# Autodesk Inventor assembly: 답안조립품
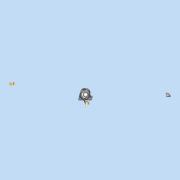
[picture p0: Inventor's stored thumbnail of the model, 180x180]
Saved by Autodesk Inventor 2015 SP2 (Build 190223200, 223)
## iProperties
Created: 2015-06
Part Number: 답안조립품
Document SubType Name: Assembly
Designer: AMC
Author: AMC
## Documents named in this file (13)
- C:\Users\AMC\Desktop\450606V1028\답안조립품.iam
- C:\Users\AMC\Desktop\450606V1028\본체.ipt
- C:\Users\AMC\Desktop\450606V1028\베어링 6204.ipt
- C:\Users\AMC\Desktop\450606V1028\크랭크 서브축.ipt
- C:\Users\AMC\Desktop\450606V1028\커넥팅 로드.ipt
- C:\Users\AMC\Desktop\450606V1028\베어링 NA 4902.ipt
- C:\Users\AMC\Desktop\450606V1028\메인 크랭크 축-구동부.ipt
- C:\Users\AMC\Desktop\450606V1028\메인커버.ipt
- C:\Users\AMC\Desktop\450606V1028\M4x0.7.ipt
- C:\Users\AMC\Desktop\450606V1028\오일실.ipt
- C:\Users\AMC\Desktop\450606V1028\피스톤 핀.ipt
- C:\Users\AMC\Desktop\450606V1028\피스톤.ipt
- C:\Users\AMC\Desktop\450606V1028\실린더헤드.ipt
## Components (6 placed, 3 different names)
1. 피스톤 핀:1
2. 피스톤:1
3. M4x0.7:1
4. M4x0.7:2
5. M4x0.7:3
6. M4x0.7:4
